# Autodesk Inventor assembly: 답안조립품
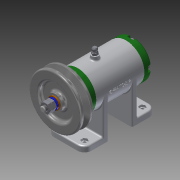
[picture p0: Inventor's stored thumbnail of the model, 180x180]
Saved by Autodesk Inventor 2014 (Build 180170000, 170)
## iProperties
Created: 2017-02
Part Number: 답안조립품
Document SubType Name: Assembly
Designer: user
Author: user
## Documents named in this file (15)
- C:\Users\user\Desktop\470208V1003\답안조립품.iam
- C:\Users\user\Desktop\470208V1003\본체.ipt
- C:\Users\user\Desktop\470208V1003\앞커버.ipt
- C:\Users\user\Desktop\470208V1003\뒤커버.ipt
- C:\Users\user\Desktop\470208V1003\볼트 M4 x 12.ipt
- C:\Users\user\Desktop\470208V1003\베어링 15 x 32 x 9.ipt
- C:\Users\user\Desktop\470208V1003\축.ipt
- C:\Users\user\Desktop\470208V1003\키 3 x 3 x 12.ipt
- C:\Users\user\Desktop\470208V1003\V벨트풀리.ipt
- C:\Users\user\Desktop\470208V1003\와셔 8x17.ipt
- C:\Users\user\Desktop\470208V1003\스프링와셔 8.ipt
- C:\Users\user\Desktop\470208V1003\너트 M 8.ipt
- C:\Users\user\Desktop\470208V1003\니플 M 6 x 0.75.ipt
- C:\Users\user\Desktop\470208V1003\와셔 6x11.5.ipt
- C:\Users\user\Desktop\470208V1003\볼트 M 6 x 8.ipt
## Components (11 placed, 3 different names)
1. KS B 2023 6002 - 15 x 32 x 9:1
2. KS B 2023 6002 - 15 x 32 x 9:2
3. V벨트풀리:1
4. ISO 4762 M4 x 12:1
5. ISO 4762 M4 x 12:3
6. ISO 4762 M4 x 12:4
7. ISO 4762 M4 x 12:5
8. ISO 4762 M4 x 12:2
9. ISO 4762 M4 x 12:6
10. ISO 4762 M4 x 12:7
11. ISO 4762 M4 x 12:8
